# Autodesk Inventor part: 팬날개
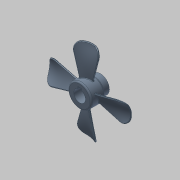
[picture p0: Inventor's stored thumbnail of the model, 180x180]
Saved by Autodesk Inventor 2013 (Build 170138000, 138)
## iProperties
Company: 한국ATC센터
Created: 2016-06
Part Number: 팬날개
Document SubType Name: Modeling
Designer: mdu
Density: 1.06 g/cm^3
Material: ABS 플라스틱
Mass: 26.2527 g
Surface Area: 149.774 cm^2
Volume: 24.7667 cm^3
Author: mdu
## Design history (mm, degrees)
sketch "스케치1"
  geometry: L1 (-15, 0)-(15, 0); L2 (-15, 0)-(-15, 17); L3 (-15, 17)-(5, 17); L4 (5, 17)-(5, 13); L5 (5, 13)-(15, 13); L6 (15, 13)-(15, 0); 2 further points
  constraints: 12 end point, 3 parallel, 2 perpendicular, 1 coincident, 1 horizontal, 1 midpoint
  dimensions: "d0" = 30 distance of L1.start L1.end; "d8" = 34 diameter of L3 L1; "d10" = 26 diameter of L5 L1; "d32" = 20 distance of L2.end L3.end
revolve "회전1" sketch "스케치1" stored, may be unused: angle "d11" = 90 deg
node "작업 평면2"
sketch "스케치7"
  geometry: L1 (-15, 17)-(5, 17) reference; L2 (-15, -17)-(5, -17) reference; L3 (-5, 17)-(-5, -17); A1 r 35 centre (-36.399, -13.457) between (-2, -7) and (-8, 7); 1 further point
  constraints: 2 end point, 2 midpoint, 2 point on circle, 1 centre point
  dimensions: "d36" = 35 radius of A1; "d37" = 10 distance from line of A1.start L2; "d38" = 10 distance from line of A1.end L1; "d45" = 3 distance from line of A1.end L3; "d46" = 3 distance from line of A1.start L3
sketch "3D 스케치1"
  geometry: L1 through (0, 0) direction (1, 0) reference; L2 through (0, 0) direction (1, 0) reference; 13 other entities
  constraints: 2 collinear
  node "투영 원본 위치 스케치7"
sketch "스케치8"
  geometry: L1 (-15, 17)-(5, 17) reference; L2 (-15, -17)-(5, -17) reference; L3 (-5, 17)-(-5, -17); A1 r 30 centre (-28.74, -3.591) between (-3, -19) and (-9, 19); 1 further point
  constraints: 2 end point, 2 midpoint, 2 point on circle, 1 centre point
  dimensions: "d43" = 30 radius of A1; "d47" = 4 distance from line of A1.end L3; "d48" = 2 distance from line of A1.start L3; "d58" = 2 distance from line of A1.end L1; "d59" = 2 distance from line of A1.start L2
sketch "3D 스케치2"
sketch "3D 스케치3"
feature "경계 패치1" sketch "3D 스케치2", "3D 스케치3" dims "d50" = 0
feature "연장1" dims "d55" = 2
feature "두껍게 하기1" dims "d51" = 2, "d52" = 2
sketch "스케치9"
  geometry: C1 r 59 at (0, 0); 1 further point
  constraints: 1 centre point, 1 coincident
  dimensions: "d60" = 118 diameter of C1
extrude "돌출2" sketch "스케치9" distance "d62" = 200; taper "d63" = 0 deg
fillet "모깎기6" dims "d64" = 10
fillet "모깎기7" dims "d66" = 0.8
fillet "모깎기8" dims "d67" = 0.8
sketch "스케치2"
  geometry: L1 (-2.5, 8.124)-(-2.5, 10.8); L2 (-2.5, 10.8)-(2.5, 10.8); L3 (2.5, 10.8)-(2.5, 8.124); A1 r 8.5 centre (0, 0) between (-2.5, 8.124) and (2.5, 8.124); 1 further point
  constraints: 6 end point, 2 parallel, 2 point on circle, 1 centre point, 1 coincident, 1 horizontal, 1 vertical
  dimensions: "d12" = 17 diameter of A1; "d13" = 5 distance of L1.end L2.end; "d14" = 19.3 dimension on A1 L2 (computed from d12)
extrude "돌출1" cut sketch "스케치2" stored distance "d15" = 10; taper "d16" = 0 deg
chamfer "모따기1" distance "d17" = 1; stored, may be unused: second distance "d18" = 2, angle "d19" = 45 deg
node "작업 평면1"
sketch "스케치3"
  geometry: L1 (5, -13)-(5, 13) reference; 3 further points
  constraints: 1 horizontal alignment, 1 midpoint
  dimensions: "d20" = 5 distance from line of L1 point (0, 0)
hole "구멍1" sketch "스케치3" at (0, 0) diameter "d21" = 3.242; stored, may be unused: countersink angle "d25" = 90 deg, drill point angle "d27" = 118 deg; dims "d22" = 6, "d23" = 4, "d24" = 2, "d26" = 8
fillet "모깎기9" dims "d77" = 2
fillet "모깎기10" dims "d78" = 2
fillet "모깎기11" dims "d79" = 2
node "솔리드1"
pattern_circular "원형 패턴1" dims "d69" = 360 deg
pattern_circular "원형 패턴2" dims angle "d72" = 360 deg
pattern_circular "원형 패턴3" dims angle "d75" = 360 deg
node "투영 원본 위치 스케치8"
node "곡면1"
node "곡면2"
node "곡면3"
node "곡면4"
feature "경계 패치2"
feature "경계 패치3"
feature "경계 패치4"
